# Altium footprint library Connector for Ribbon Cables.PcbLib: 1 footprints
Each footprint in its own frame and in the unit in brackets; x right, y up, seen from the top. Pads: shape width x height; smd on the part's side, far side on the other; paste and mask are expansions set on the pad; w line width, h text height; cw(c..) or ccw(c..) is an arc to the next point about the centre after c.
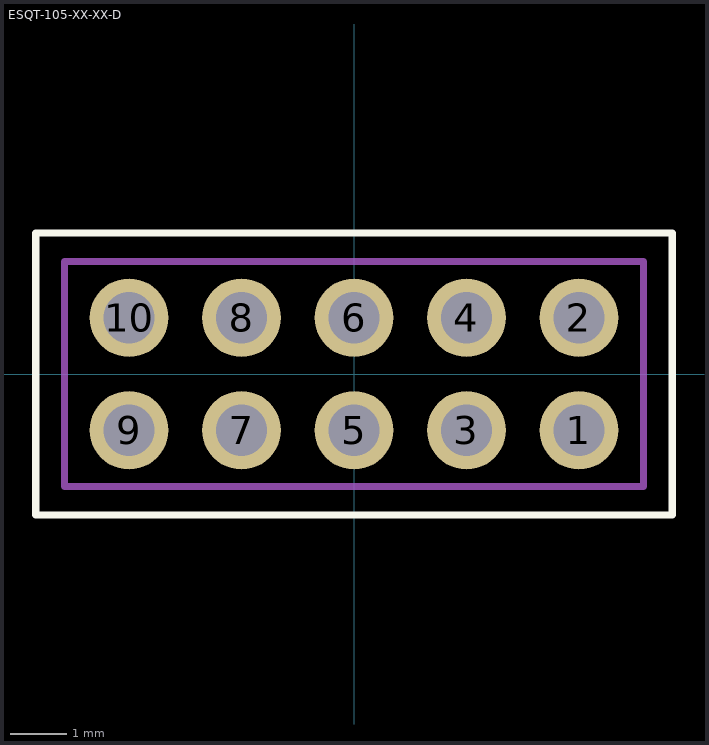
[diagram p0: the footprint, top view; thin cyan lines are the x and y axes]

## ESQT-105-XX-XX-D [mil]
pads (10):
  round 55 hole 36: 1(157.48,-39.37) 2(157.48,39.37) 3(78.74,-39.37) 4(78.74,39.37) 5(0,-39.37) 6(0,39.37) 7(-78.74,-39.37) 8(-78.74,39.37) 9(-157.48,-39.37) 10(-157.48,39.37)
Top Overlay:
  lines w5: -222.7,-98.75 222.7,-98.75 222.7,98.75 -222.7,98.75 -222.7,-98.75
Mechanical 13:
  lines w5: -202.7,-78.75 202.7,-78.75 202.7,78.75 -202.7,78.75 -202.7,-78.75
